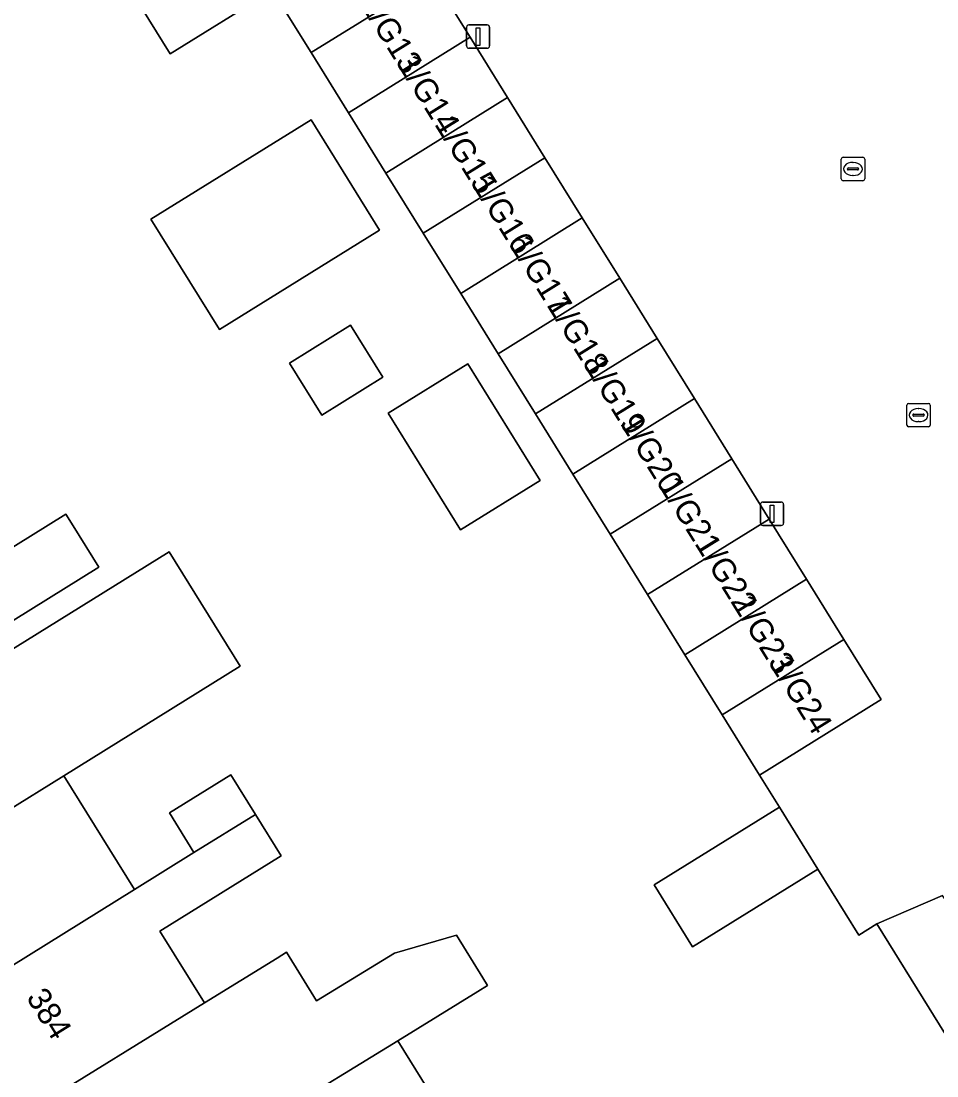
# Model space of a CAD drawing. Extents: x 160023 to 161302, y 384750 to 385707.
# Drawn here: x 160069.82 to 160109.01, y 385265.36 to 385310.49 of the extents above; entities that cross this region are included whole.
import ezdxf

# ---------------------------------------------------------------- set-up
doc = ezdxf.new("R2010")
doc.units = 0
for name, color, linetype in [('IMGEO_Erf', 7, 'Continuous'), ('IMGEO_Kolk', 7, 'Continuous'), ('IMGEO_Lichtmast', 7, 'Continuous'), ('IMGEO_Pand', 7, 'Continuous'), ('IMGEO_Pand_nummerreeks', 7, 'Continuous'), ('IMGEO_Rijbaan_lokaal_open', 7, 'Continuous')]:
    doc.layers.add(name, color=color, linetype=linetype)

msp = doc.modelspace()

# ---------------------------------------------------------------- linework, layer by layer
at = {"layer": 'IMGEO_Erf'}
for points in [[(160152.014, 385315.353), (160133.213, 385328.221), (160132.92, 385328.421), (160128.791, 385322.11), (160120.909, 385304.204), (160118.514, 385298.764), (160117.264, 385295.926), (160116.015, 385293.089), (160114.766, 385290.253), (160113.701, 385287.743), (160114.618, 385287.345), (160116.68, 385286.451), (160114.754, 385282.009), (160113.13, 385278.262), (160115.091, 385275.318), (160112.419, 385273.539), (160114.46, 385270.474), (160117.839, 385265.396), (160112.507, 385262.087), (160109.628, 385266.727), (160106.437, 385271.869)], [(160080.576, 385311.813), (160076.198, 385309.096), (160073.131, 385314.037)], [(160106.437, 385271.869), (160105.671, 385271.378), (160103.91, 385274.216), (160098.554, 385270.892), (160096.909, 385273.542), (160102.265, 385276.866), (160101.418, 385278.23), (160099.819, 385280.806), (160098.22, 385283.383), (160096.621, 385285.959), (160095.022, 385288.535), (160093.423, 385291.111), (160091.824, 385293.688), (160090.226, 385296.264), (160088.627, 385298.84), (160087.028, 385301.417), (160085.429, 385303.993), (160083.83, 385306.569), (160082.231, 385309.145), (160080.632, 385311.722)], [(160066.646, 385286.247), (160071.731, 385289.403), (160072.041, 385288.904), (160073.139, 385287.134), (160068.063, 385283.985)], [(160068.608, 385283.106), (160076.153, 385287.789), (160079.194, 385282.889), (160071.649, 385278.206), (160073.616, 385275.036), (160074.67, 385273.337), (160077.214, 385274.915), (160076.16, 385276.615), (160078.792, 385278.248), (160079.847, 385276.548), (160080.945, 385274.779), (160075.759, 385271.561), (160077.664, 385268.491), (160080.771, 385270.407), (160081.172, 385270.655), (160082.464, 385268.574), (160085.79, 385270.611), (160088.446, 385271.384), (160089.575, 385269.565), (160089.778, 385269.238), (160089.363, 385268.982), (160085.931, 385266.869), (160087.477, 385264.377)]]:
    msp.add_lwpolyline(points, dxfattribs=at)
for points in [[(160078.302, 385297.294), (160075.368, 385302.021), (160082.223, 385306.275), (160085.156, 385301.549)], [(160082.681, 385293.628), (160081.298, 385295.856), (160083.915, 385297.48), (160085.297, 385295.252)], [(160088.624, 385288.727), (160085.53, 385293.715), (160088.932, 385295.826), (160092.026, 385290.838)]]:
    msp.add_lwpolyline(points, close=True, dxfattribs=at)
at = {"layer": 'IMGEO_Kolk'}
for p, q in [((160104.916, 385303.74), (160104.916, 385304.592)), ((160104.991, 385304.666), (160105.843, 385304.666)), ((160105.917, 385304.592), (160105.917, 385303.74)), ((160105.175, 385304.16), (160105.175, 385304.172)), ((160105.613, 385304.123), (160105.215, 385304.123)), ((160105.218, 385304.209), (160105.616, 385304.209)), ((160105.404, 385304.446), (160105.429, 385304.446)), ((160105.659, 385304.172), (160105.659, 385304.16)), ((160105.843, 385303.666), (160104.991, 385303.666)), ((160105.427, 385303.886), (160105.402, 385303.886)), ((160107.798, 385294.137), (160108.65, 385294.137)), ((160107.723, 385293.211), (160107.723, 385294.063)), ((160107.982, 385293.631), (160107.982, 385293.643)), ((160108.025, 385293.68), (160108.423, 385293.68)), ((160108.211, 385293.917), (160108.236, 385293.917)), ((160108.466, 385293.643), (160108.466, 385293.631)), ((160108.724, 385294.063), (160108.724, 385293.211)), ((160108.42, 385293.594), (160108.022, 385293.594)), ((160108.234, 385293.357), (160108.209, 385293.357)), ((160108.65, 385293.137), (160107.798, 385293.137))]:
    msp.add_line(p, q, dxfattribs=at)
for points in [[(160104.916, 385303.74), (160104.916, 385304.592)], [(160104.991, 385304.666), (160105.843, 385304.666)], [(160105.917, 385304.592), (160105.917, 385303.74)], [(160105.843, 385303.666), (160104.991, 385303.666)], [(160107.798, 385294.137), (160108.65, 385294.137)], [(160107.723, 385293.211), (160107.723, 385294.063)], [(160108.724, 385294.063), (160108.724, 385293.211)], [(160108.65, 385293.137), (160107.798, 385293.137)]]:
    msp.add_lwpolyline(points, dxfattribs=at)
for centre, radius, start, end in [((160104.993, 385304.59), 0.0765, 91.552, 178.448), ((160104.993, 385304.59), 0.0765, 91.552, 178.448), ((160105.841, 385304.59), 0.0765, 1.552, 88.448), ((160105.841, 385304.59), 0.0765, 1.552, 88.448), ((160105.215, 385304.169), 0.0403, 85.8775, 175.7526), ((160105.212, 385304.159), 0.0366, 178.938, 274.7102), ((160105.616, 385304.166), 0.043, 264.8664, 352.4533), ((160105.62, 385304.171), 0.0386, 1.7309, 96.639), ((160104.993, 385303.742), 0.0765, 181.552, 268.448), ((160104.993, 385303.742), 0.0765, 181.552, 268.448), ((160105.841, 385303.742), 0.0765, 271.552, 358.448), ((160105.841, 385303.742), 0.0765, 271.552, 358.448), ((160107.8, 385294.061), 0.0765, 91.552, 178.448), ((160107.8, 385294.061), 0.0765, 91.552, 178.448), ((160108.648, 385294.061), 0.0765, 1.552, 88.448), ((160108.648, 385294.061), 0.0765, 1.552, 88.448), ((160108.022, 385293.64), 0.0403, 85.8775, 175.7526), ((160108.427, 385293.642), 0.0386, 1.7309, 96.639), ((160107.8, 385293.213), 0.0765, 181.552, 268.448), ((160107.8, 385293.213), 0.0765, 181.552, 268.448), ((160108.019, 385293.63), 0.0366, 178.938, 274.7102), ((160108.423, 385293.637), 0.043, 264.8664, 352.4533), ((160108.648, 385293.213), 0.0765, 271.552, 358.448), ((160108.648, 385293.213), 0.0765, 271.552, 358.448)]:
    msp.add_arc(centre, radius, start, end, dxfattribs=at)
for centre, major_axis, ratio, start_param, end_param in [((160105.403, 385304.166), (-0.387, 0.002), 0.722429, 4.712389, 7.853982), ((160105.428, 385304.166), (-0.39, 0.002), 0.717154, 1.570796, 4.712389), ((160108.21, 385293.637), (-0.387, 0.002), 0.722429, 4.712389, 7.853982), ((160108.235, 385293.637), (-0.39, 0.002), 0.717154, 1.570796, 4.712389)]:
    msp.add_ellipse(centre, major_axis=major_axis, ratio=ratio, start_param=start_param, end_param=end_param, dxfattribs=at)
at = {"layer": 'IMGEO_Lichtmast'}
for p, q in [((160088.877, 385309.429), (160088.877, 385310.229)), ((160088.877, 385310.229), (160088.877, 385309.429)), ((160088.977, 385310.329), (160089.767, 385310.329)), ((160089.767, 385310.329), (160088.977, 385310.329)), ((160089.867, 385310.229), (160089.867, 385309.429)), ((160089.867, 385309.429), (160089.867, 385310.229)), ((160089.767, 385309.329), (160088.977, 385309.329)), ((160088.977, 385309.329), (160089.767, 385309.329)), ((160101.455, 385289.012), (160101.455, 385289.812)), ((160101.455, 385289.812), (160101.455, 385289.012)), ((160101.555, 385289.912), (160102.345, 385289.912)), ((160102.345, 385289.912), (160101.555, 385289.912)), ((160102.445, 385289.812), (160102.445, 385289.012)), ((160102.445, 385289.012), (160102.445, 385289.812)), ((160102.345, 385288.912), (160101.555, 385288.912)), ((160101.555, 385288.912), (160102.345, 385288.912))]:
    msp.add_line(p, q, dxfattribs=at)
for points in [[(160089.297, 385310.204), (160089.447, 385310.204), (160089.447, 385309.454), (160089.297, 385309.454), (160089.297, 385310.204)], [(160101.875, 385289.787), (160102.025, 385289.787), (160102.025, 385289.037), (160101.875, 385289.037), (160101.875, 385289.787)]]:
    msp.add_lwpolyline(points, dxfattribs=at)
for centre, start, end in [((160088.977, 385310.229), 90, 180), ((160088.977, 385310.229), 90, 180), ((160089.767, 385310.229), 0, 90), ((160089.767, 385310.229), 360, 90), ((160088.977, 385309.429), 180, 270), ((160088.977, 385309.429), 180, 270), ((160089.767, 385309.429), 270, 0), ((160089.767, 385309.429), 270, 0), ((160101.555, 385289.812), 90, 180), ((160101.555, 385289.812), 90, 180), ((160102.345, 385289.812), 0, 90), ((160102.345, 385289.812), 360, 90), ((160101.555, 385289.012), 180, 270), ((160101.555, 385289.012), 180, 270), ((160102.345, 385289.012), 270, 0), ((160102.345, 385289.012), 270, 0)]:
    msp.add_arc(centre, 0.1, start, end, dxfattribs=at)
at = {"layer": 'IMGEO_Pand'}
for points in [[(160080.576, 385311.813), (160079.033, 385314.298), (160077.982, 385315.993), (160077.737, 385316.388), (160077.51, 385316.754), (160077.227, 385316.578), (160076.797, 385316.312), (160073.131, 385314.037), (160076.198, 385309.096)], [(160080.632, 385311.722), (160082.231, 385309.145), (160087.437, 385312.376), (160085.838, 385314.953)], [(160082.231, 385309.145), (160083.83, 385306.569), (160089.036, 385309.8), (160087.437, 385312.376)], [(160090.635, 385307.224), (160089.036, 385309.8), (160083.83, 385306.569), (160085.429, 385303.993)], [(160085.429, 385303.993), (160087.028, 385301.417), (160092.234, 385304.648), (160090.635, 385307.224)], [(160075.368, 385302.021), (160078.302, 385297.294), (160085.156, 385301.549), (160082.223, 385306.275)], [(160093.833, 385302.071), (160092.234, 385304.648), (160087.028, 385301.417), (160088.627, 385298.84)], [(160095.432, 385299.495), (160093.833, 385302.071), (160088.627, 385298.84), (160090.226, 385296.264)], [(160090.226, 385296.264), (160091.824, 385293.688), (160097.03, 385296.919), (160095.432, 385299.495)], [(160081.298, 385295.856), (160082.681, 385293.628), (160085.297, 385295.252), (160083.915, 385297.48)], [(160098.629, 385294.342), (160097.03, 385296.919), (160091.824, 385293.688), (160093.423, 385291.111)], [(160085.53, 385293.715), (160088.624, 385288.727), (160092.026, 385290.838), (160088.932, 385295.826)], [(160100.228, 385291.766), (160098.629, 385294.342), (160093.423, 385291.111), (160095.022, 385288.535)], [(160101.827, 385289.19), (160100.228, 385291.766), (160095.022, 385288.535), (160096.621, 385285.959)], [(160073.139, 385287.134), (160072.041, 385288.904), (160071.731, 385289.403), (160066.646, 385286.247), (160065.028, 385288.855), (160057.471, 385284.178), (160057.634, 385283.915), (160057.263, 385283.224), (160058.371, 385281.439), (160059.126, 385281.463), (160060.481, 385279.28), (160064.73, 385281.917), (160068.063, 385283.985)], [(160101.827, 385289.19), (160096.621, 385285.959), (160098.22, 385283.383), (160103.426, 385286.614)], [(160068.608, 385283.106), (160065.275, 385281.038), (160061.026, 385278.402), (160062.329, 385276.302), (160061.958, 385275.611), (160063.06, 385273.836), (160063.838, 385273.861), (160064.062, 385273.5), (160071.649, 385278.206), (160079.194, 385282.889), (160076.153, 385287.789)], [(160103.426, 385286.614), (160098.22, 385283.383), (160099.819, 385280.806), (160105.025, 385284.037)], [(160105.025, 385284.037), (160099.819, 385280.806), (160101.418, 385278.23), (160106.624, 385281.461)], [(160073.616, 385275.036), (160071.649, 385278.206), (160064.062, 385273.5), (160064.284, 385273.142), (160063.915, 385272.454), (160065.007, 385270.695), (160065.793, 385270.72), (160067.087, 385268.634), (160074.67, 385273.337)], [(160077.214, 385274.915), (160079.847, 385276.548), (160078.792, 385278.248), (160076.16, 385276.615)], [(160075.759, 385271.561), (160080.945, 385274.779), (160079.847, 385276.548), (160077.214, 385274.915), (160074.67, 385273.337), (160067.087, 385268.634), (160068.381, 385266.549), (160068.009, 385265.854), (160069.064, 385264.154), (160069.864, 385264.179), (160070.088, 385263.817), (160077.664, 385268.491)], [(160102.265, 385276.866), (160096.909, 385273.542), (160098.554, 385270.892), (160103.91, 385274.216)], [(160106.437, 385271.869), (160109.628, 385266.727), (160111.909, 385268.179), (160111.219, 385269.263), (160111.51, 385269.448), (160111.406, 385269.611), (160111.508, 385269.676), (160109.24, 385273.084)], [(160085.931, 385266.869), (160089.363, 385268.982), (160089.778, 385269.238), (160089.575, 385269.565), (160088.446, 385271.384), (160085.79, 385270.611), (160082.464, 385268.574), (160081.172, 385270.655), (160080.771, 385270.407), (160077.664, 385268.491), (160070.088, 385263.817), (160070.313, 385263.455), (160069.945, 385262.767), (160071.041, 385261), (160071.808, 385261.024), (160073.103, 385258.937), (160080.677, 385263.635)], [(160082.307, 385261.169), (160087.477, 385264.377), (160085.931, 385266.869), (160080.677, 385263.635), (160073.103, 385258.937), (160074.399, 385256.849), (160074.035, 385256.17), (160075.135, 385254.399), (160075.905, 385254.423), (160076.115, 385254.085), (160083.754, 385258.837)]]:
    msp.add_lwpolyline(points, close=True, dxfattribs=at)
at = {"layer": 'IMGEO_Rijbaan_lokaal_open'}
msp.add_lwpolyline([(160087.437, 385312.376), (160089.036, 385309.8), (160090.635, 385307.224), (160092.234, 385304.648), (160093.833, 385302.071), (160095.432, 385299.495), (160097.03, 385296.919), (160098.629, 385294.342), (160100.228, 385291.766), (160101.827, 385289.19), (160103.426, 385286.614), (160105.025, 385284.037), (160106.624, 385281.461), (160101.418, 385278.23), (160102.265, 385276.866), (160103.91, 385274.216), (160105.671, 385271.378), (160106.437, 385271.869), (160109.24, 385273.084)], dxfattribs=at)

# ---------------------------------------------------------------- texts
at = {"layer": 'IMGEO_Pand_nummerreeks'}
for s, rotation, p in [('1/G13', 301.8248, (160084.281, 385311.242)), ('1/G14', 301.8248, (160085.88, 385308.665)), ('1/G15', 301.8248, (160087.479, 385306.089)), ('1/G16', 301.8248, (160089.078, 385303.513)), ('1/G17', 301.8248, (160090.677, 385300.937)), ('1/G18', 301.8248, (160092.277, 385298.358)), ('1/G19', 301.8248, (160093.873, 385295.787)), ('1/G20', 301.8248, (160095.427, 385293.283)), ('1/G21', 301.8248, (160097.082, 385290.615)), ('1/G22', 301.8248, (160098.62, 385288.138)), ('1/G23', 301.8248, (160100.222, 385285.556)), ('1/G24', 301.8248, (160101.821, 385282.98)), ('384', 301.862, (160070.012, 385268.719))]:
    msp.add_text(s, height=1, rotation=rotation, dxfattribs=at).set_placement(p)

doc.saveas('drawing.dxf')
